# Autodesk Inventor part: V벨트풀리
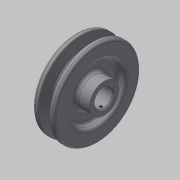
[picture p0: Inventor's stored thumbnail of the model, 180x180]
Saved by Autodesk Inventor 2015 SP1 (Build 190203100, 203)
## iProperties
Created: 2015-11
Part Number: V벨트풀리
Material: 강철, 탄소
Document SubType Name: Modeling
Designer: mduedu
Density: 1 g/cm^3
Appearance: 기본값
Author: mduedu
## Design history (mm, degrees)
sketch "스케치1"
  geometry: L1 (-9.5, 0)-(9.5, 0); L2 (0, 0)-(0, 37.7); L3 (-4.825, 37.7)-(-9.5, 37.7); L4 (-9.5, 37.7)-(-9.5, 0); L5 (0, 28.7)-(-2.074, 28.7); L6 (-2.074, 28.7)-(-4.825, 37.7); L7 (4.825, 37.7)-(9.5, 37.7); L8 (9.5, 37.7)-(9.5, 0); L9 (0, 28.7)-(2.074, 28.7); L10 (2.074, 28.7)-(4.825, 37.7); L11 (-9.5, 35)-(9.5, 35); 3 further points
  constraints: 22 end point, 7 point on line, 4 perpendicular, 3 symmetric about line, 1 coincident, 1 horizontal, 1 horizontal alignment, 1 midpoint, 1 vertical
  dimensions: "d0" = 19 distance of L1.start L1.end; "d2" = 75.4 diameter of L2.end L1 (derived); "d3" = 34 deg angle of L10 L6; "d4" = 6.3 distance between parallel lines of L11 L9; "d5" = 2.7 distance between parallel lines of L7 L11; "d6" = 8 distance of point (4, 35) point (-4, 35); "d7" = 70 diameter of L11 L1
revolve "회전1" sketch "스케치1" stored, may be unused: angle "d8" = 90 deg
sketch "스케치2"
  geometry: C1 r 24 at (0, 0); C2 r 13 at (0, 0); 1 further point
  constraints: 2 centre point, 2 coincident
  dimensions: "d9" = 48 diameter of C1; "d10" = 26 diameter of C2
extrude "돌출1" cut sketch "스케치2" distance "d11" = 6; taper "d12" = 0 deg
extrude "돌출3" join sketch "스케치2" distance "d37" = 6; taper "d38" = 0 deg
fillet "모깎기1" dims "d13" = 3
fillet "모깎기2" dims "d14" = 3
fillet "모깎기3" dims "d15" = 1, "d16" = 0.5, "d17" = 2
hole "구멍1" diameter "d20" = 16; stored, may be unused: countersink angle "d24" = 90 deg, drill point angle "d26" = 118 deg; dims "d21" = 6, "d22" = 4, "d23" = 2, "d25" = 8, "d53" = 10, "d54" = 10
sketch "스케치3"
  geometry: L1 (-2.5, 0)-(2.5, 0); L2 (2.5, 0)-(2.5, 10.3); L3 (2.5, 10.3)-(-2.5, 10.3); L4 (-2.5, 10.3)-(-2.5, 0); 2 further points
  constraints: 8 end point, 2 parallel, 1 coincident, 1 horizontal, 1 midpoint, 1 perpendicular
  dimensions: "d27" = 5 distance of L2.end L3.end; "d29" = 10.3 distance of L3.end L1.start
extrude "돌출2" cut sketch "스케치3" stored distance "d30" = 6; taper "d31" = 0 deg
chamfer "모따기1" distance "d32" = 1; stored, may be unused: second distance "d33" = 2, angle "d34" = 45 deg
node "작업 평면1"
sketch "스케치4"
  geometry: L1 (19, -27)-(19, 27) reference; 2 further points
  constraints: 1 horizontal alignment
  dimensions: "d52" = 22 distance from line of L1 point (-3, 0)
hole "구멍2" sketch "스케치4" at (-3, 0) diameter "d42" = 2.459; stored, may be unused: countersink angle "d46" = 90 deg, drill point angle "d48" = 118 deg; dims "d43" = 6, "d44" = 4, "d45" = 2, "d47" = 8
chamfer "모따기3" distance "d58" = 1; stored, may be unused: second distance "d59" = 2, angle "d60" = 45 deg
node "솔리드1"
mirror "대칭1"
